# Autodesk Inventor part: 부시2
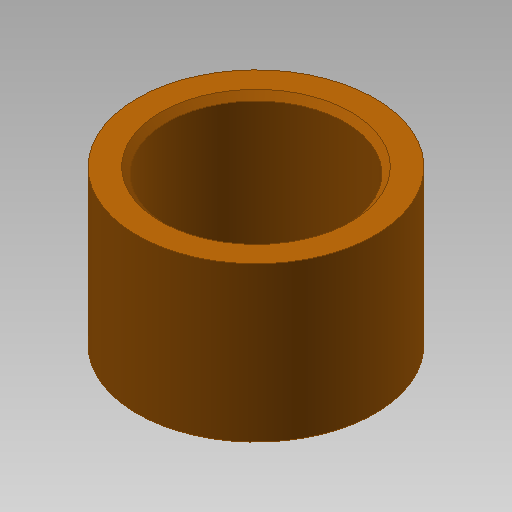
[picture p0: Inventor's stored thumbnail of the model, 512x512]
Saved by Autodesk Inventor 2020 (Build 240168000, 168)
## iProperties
Created: 2016-08
Part Number: 부시2
Material: 강철, 탄소
Document SubType Name: Modeling
Designer: mduedu
Density: 7.87 g/cm^3
Appearance: 주황색
Author: mduedu
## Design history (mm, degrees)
sketch "스케치1"
  geometry: C1 r 7.5 at (0, 0); C2 r 10 at (0, 0); 1 further point
  constraints: 2 centre point, 2 coincident
  dimensions: "d0" = 15 diameter of C1; "d1" = 20 diameter of C2
extrude "돌출1" new body sketch "스케치1" stored distance "d2" = 13; taper "d3" = 0 deg
chamfer "모따기1" distance "d4" = 0.5; stored, may be unused: second distance "d5" = 2, angle "d6" = 45 deg
node "솔리드1"
